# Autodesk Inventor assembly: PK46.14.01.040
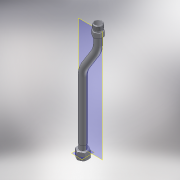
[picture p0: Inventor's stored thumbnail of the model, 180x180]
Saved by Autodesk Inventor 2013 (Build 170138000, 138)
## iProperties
Created: 2005-03
Part Number: PK46.14.01.040
Document SubType Name: Assembly
Designer: elarisa
Manufacturer: Standard
Standards Organization: Custom
Author: elarisa
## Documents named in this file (5)
- C:\Product Design Suite 2013\Data\Assemblies\PK46.14.01.040.iam
- C:\Product Design Suite 2013\Data\Parts\PK46.14.01.017.ipt
- C:\Product Design Suite 2013\Data\Parts\027.03.03.003.ipt
- C:\Product Design Suite 2013\Data\Parts\027.07.02.004.ipt
- C:\Product Design Suite 2013\Data\Parts\027.08.00.003.ipt
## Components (4 placed, 4 different names)
1. PK46.14.01.017:1 — Insert:3, Insert:2
2. 027.07.02.004:1 — Insert:1, Insert:2
3. 027.08.00.003:1 — Insert:1
4. 027.03.03.003:1 — Insert:3
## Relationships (3: Insert 3)
- Insert:1: 027.07.02.004:1 ↔ 027.08.00.003:1
- Insert:3: PK46.14.01.017:1 ↔ 027.03.03.003:1
- Insert:2: PK46.14.01.017:1 ↔ 027.07.02.004:1
